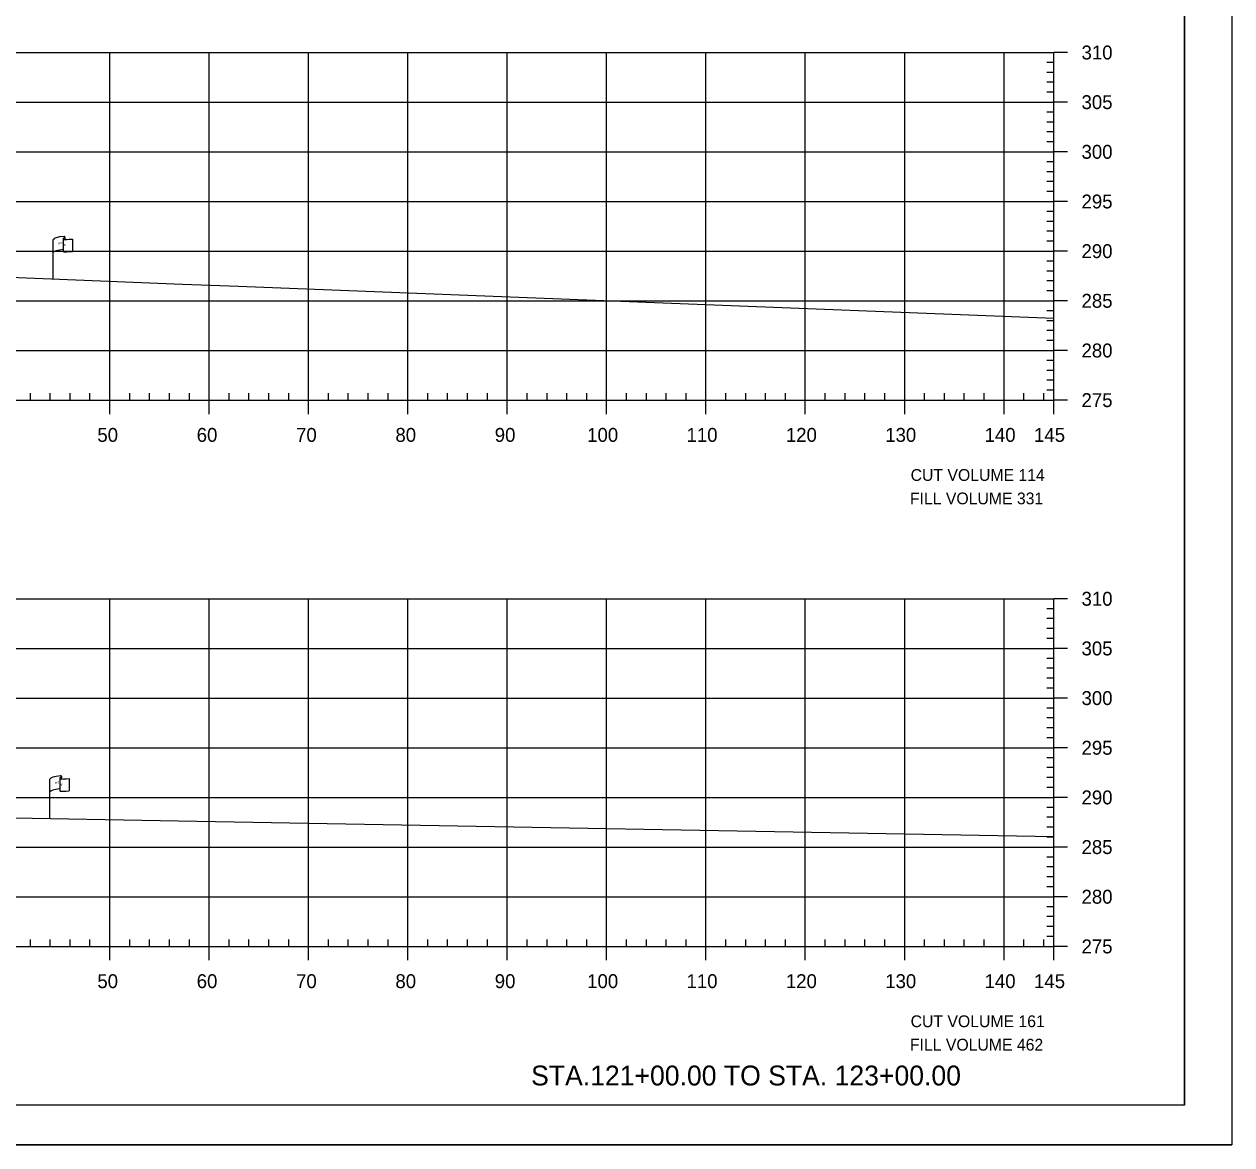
# Model space of a CAD drawing. Extents: x 1370843 to 1371177, y 380307 to 382654.
# Drawn here: x 1371055.1 to 1371176.6, y 382014.2 to 382127 of the extents above; entities that cross this region are included whole.
import ezdxf

# ---------------------------------------------------------------- set-up
doc = ezdxf.new("R2010")
doc.units = 0
for name, color, linetype in [('R_Axis', 7, 'Continuous'), ('R_Axis Annot', 7, 'Continuous'), ('R_Border', 7, 'Continuous'), ('R_Border Notes', 7, 'Continuous'), ('R_Draft', 7, 'Continuous'), ('R_Exist Surface', 7, 'Continuous'), ('R_Grid', 7, 'Continuous'), ('R_No Plot', 7, 'Continuous'), ('R_ROW', 7, 'Continuous')]:
    doc.layers.add(name, color=color, linetype=linetype)

msp = doc.modelspace()

# ---------------------------------------------------------------- linework, layer by layer
at = {"layer": 'R_Axis'}
for p, q in [((1371158.71, 382123.15), (1371158.01, 382123.15)), ((1371158.71, 382089.15), (1371158.71, 382124.15)), ((1371160.11, 382124.15), (1371158.71, 382124.15)), ((1371158.71, 382122.15), (1371158.01, 382122.15)), ((1371158.71, 382121.15), (1371158.01, 382121.15)), ((1371158.71, 382120.15), (1371158.01, 382120.15)), ((1371158.71, 382118.15), (1371158.01, 382118.15)), ((1371160.11, 382119.15), (1371158.71, 382119.15)), ((1371158.71, 382117.15), (1371158.01, 382117.15)), ((1371158.71, 382116.15), (1371158.01, 382116.15)), ((1371158.71, 382115.15), (1371158.01, 382115.15)), ((1371160.11, 382114.15), (1371158.71, 382114.15)), ((1371158.71, 382113.15), (1371158.01, 382113.15)), ((1371158.71, 382112.15), (1371158.01, 382112.15)), ((1371158.71, 382111.15), (1371158.01, 382111.15)), ((1371158.71, 382110.15), (1371158.01, 382110.15)), ((1371160.11, 382109.15), (1371158.71, 382109.15)), ((1371158.71, 382108.15), (1371158.01, 382108.15)), ((1371158.71, 382107.15), (1371158.01, 382107.15)), ((1371158.71, 382106.15), (1371158.01, 382106.15)), ((1371158.71, 382105.15), (1371158.01, 382105.15)), ((1371160.11, 382104.15), (1371158.71, 382104.15)), ((1371158.71, 382103.15), (1371158.01, 382103.15)), ((1371158.71, 382102.15), (1371158.01, 382102.15)), ((1371158.71, 382101.15), (1371158.01, 382101.15)), ((1371158.71, 382100.15), (1371158.01, 382100.15)), ((1371160.11, 382099.15), (1371158.71, 382099.15)), ((1371158.71, 382098.15), (1371158.01, 382098.15)), ((1371158.71, 382097.15), (1371158.01, 382097.15)), ((1371158.71, 382096.15), (1371158.01, 382096.15)), ((1371158.71, 382095.15), (1371158.01, 382095.15)), ((1371160.11, 382094.15), (1371158.71, 382094.15)), ((1371158.71, 382093.15), (1371158.01, 382093.15)), ((1371158.71, 382092.15), (1371158.01, 382092.15)), ((1371158.71, 382091.15), (1371158.01, 382091.15)), ((1370868.71, 382089.15), (1371158.71, 382089.15)), ((1371055.71, 382089.15), (1371055.71, 382089.85)), ((1371057.71, 382089.15), (1371057.71, 382089.85)), ((1371059.71, 382089.15), (1371059.71, 382089.85)), ((1371061.71, 382089.15), (1371061.71, 382089.85)), ((1371063.71, 382087.75), (1371063.71, 382089.15)), ((1371065.71, 382089.15), (1371065.71, 382089.85)), ((1371067.71, 382089.15), (1371067.71, 382089.85)), ((1371069.71, 382089.15), (1371069.71, 382089.85)), ((1371071.71, 382089.15), (1371071.71, 382089.85)), ((1371073.71, 382087.75), (1371073.71, 382089.15)), ((1371075.71, 382089.15), (1371075.71, 382089.85)), ((1371077.71, 382089.15), (1371077.71, 382089.85)), ((1371079.71, 382089.15), (1371079.71, 382089.85)), ((1371081.71, 382089.15), (1371081.71, 382089.85)), ((1371083.71, 382087.75), (1371083.71, 382089.15)), ((1371085.71, 382089.15), (1371085.71, 382089.85)), ((1371087.71, 382089.15), (1371087.71, 382089.85)), ((1371089.71, 382089.15), (1371089.71, 382089.85)), ((1371091.71, 382089.15), (1371091.71, 382089.85)), ((1371093.71, 382087.75), (1371093.71, 382089.15)), ((1371095.71, 382089.15), (1371095.71, 382089.85)), ((1371097.71, 382089.15), (1371097.71, 382089.85)), ((1371099.71, 382089.15), (1371099.71, 382089.85)), ((1371101.71, 382089.15), (1371101.71, 382089.85)), ((1371103.71, 382087.75), (1371103.71, 382089.15)), ((1371105.71, 382089.15), (1371105.71, 382089.85)), ((1371107.71, 382089.15), (1371107.71, 382089.85)), ((1371109.71, 382089.15), (1371109.71, 382089.85)), ((1371111.71, 382089.15), (1371111.71, 382089.85)), ((1371113.71, 382087.75), (1371113.71, 382089.15)), ((1371115.71, 382089.15), (1371115.71, 382089.85)), ((1371117.71, 382089.15), (1371117.71, 382089.85)), ((1371119.71, 382089.15), (1371119.71, 382089.85)), ((1371121.71, 382089.15), (1371121.71, 382089.85)), ((1371123.71, 382087.75), (1371123.71, 382089.15)), ((1371125.71, 382089.15), (1371125.71, 382089.85)), ((1371127.71, 382089.15), (1371127.71, 382089.85)), ((1371129.71, 382089.15), (1371129.71, 382089.85)), ((1371131.71, 382089.15), (1371131.71, 382089.85)), ((1371133.71, 382087.75), (1371133.71, 382089.15)), ((1371135.71, 382089.15), (1371135.71, 382089.85)), ((1371137.71, 382089.15), (1371137.71, 382089.85)), ((1371139.71, 382089.15), (1371139.71, 382089.85)), ((1371141.71, 382089.15), (1371141.71, 382089.85)), ((1371143.71, 382087.75), (1371143.71, 382089.15)), ((1371145.71, 382089.15), (1371145.71, 382089.85)), ((1371147.71, 382089.15), (1371147.71, 382089.85)), ((1371149.71, 382089.15), (1371149.71, 382089.85)), ((1371151.71, 382089.15), (1371151.71, 382089.85)), ((1371153.71, 382087.75), (1371153.71, 382089.15)), ((1371155.71, 382089.15), (1371155.71, 382089.85)), ((1371157.71, 382089.15), (1371157.71, 382089.85)), ((1371158.71, 382090.15), (1371158.01, 382090.15)), ((1371158.71, 382087.75), (1371158.71, 382089.15)), ((1371160.11, 382089.15), (1371158.71, 382089.15)), ((1371158.71, 382034.15), (1371158.71, 382069.15)), ((1371160.11, 382069.15), (1371158.71, 382069.15)), ((1371158.71, 382068.15), (1371158.01, 382068.15)), ((1371158.71, 382067.15), (1371158.01, 382067.15)), ((1371158.71, 382066.15), (1371158.01, 382066.15)), ((1371158.71, 382065.15), (1371158.01, 382065.15)), ((1371160.11, 382064.15), (1371158.71, 382064.15)), ((1371158.71, 382063.15), (1371158.01, 382063.15)), ((1371158.71, 382062.15), (1371158.01, 382062.15)), ((1371158.71, 382061.15), (1371158.01, 382061.15)), ((1371158.71, 382060.15), (1371158.01, 382060.15)), ((1371160.11, 382059.15), (1371158.71, 382059.15)), ((1371158.71, 382058.15), (1371158.01, 382058.15)), ((1371158.71, 382057.15), (1371158.01, 382057.15)), ((1371158.71, 382056.15), (1371158.01, 382056.15)), ((1371158.71, 382055.15), (1371158.01, 382055.15)), ((1371160.11, 382054.15), (1371158.71, 382054.15)), ((1371158.71, 382053.15), (1371158.01, 382053.15)), ((1371158.71, 382052.15), (1371158.01, 382052.15)), ((1371158.71, 382051.15), (1371158.01, 382051.15)), ((1371158.71, 382050.15), (1371158.01, 382050.15)), ((1371160.11, 382049.15), (1371158.71, 382049.15)), ((1371158.71, 382048.15), (1371158.01, 382048.15)), ((1371158.71, 382047.15), (1371158.01, 382047.15)), ((1371158.71, 382046.15), (1371158.01, 382046.15)), ((1371158.71, 382045.15), (1371158.01, 382045.15)), ((1371160.11, 382044.15), (1371158.71, 382044.15)), ((1371158.71, 382043.15), (1371158.01, 382043.15)), ((1371158.71, 382042.15), (1371158.01, 382042.15)), ((1371158.71, 382041.15), (1371158.01, 382041.15)), ((1371158.71, 382040.15), (1371158.01, 382040.15)), ((1371160.11, 382039.15), (1371158.71, 382039.15)), ((1371158.71, 382038.15), (1371158.01, 382038.15)), ((1371158.71, 382037.15), (1371158.01, 382037.15)), ((1371158.71, 382036.15), (1371158.01, 382036.15)), ((1371055.71, 382034.15), (1371055.71, 382034.85)), ((1371057.71, 382034.15), (1371057.71, 382034.85)), ((1371059.71, 382034.15), (1371059.71, 382034.85)), ((1371061.71, 382034.15), (1371061.71, 382034.85)), ((1371065.71, 382034.15), (1371065.71, 382034.85)), ((1371067.71, 382034.15), (1371067.71, 382034.85)), ((1371069.71, 382034.15), (1371069.71, 382034.85)), ((1371071.71, 382034.15), (1371071.71, 382034.85)), ((1371075.71, 382034.15), (1371075.71, 382034.85)), ((1371077.71, 382034.15), (1371077.71, 382034.85)), ((1371079.71, 382034.15), (1371079.71, 382034.85)), ((1371081.71, 382034.15), (1371081.71, 382034.85)), ((1371085.71, 382034.15), (1371085.71, 382034.85)), ((1371087.71, 382034.15), (1371087.71, 382034.85)), ((1371089.71, 382034.15), (1371089.71, 382034.85)), ((1371091.71, 382034.15), (1371091.71, 382034.85)), ((1371095.71, 382034.15), (1371095.71, 382034.85)), ((1371097.71, 382034.15), (1371097.71, 382034.85)), ((1371099.71, 382034.15), (1371099.71, 382034.85)), ((1371101.71, 382034.15), (1371101.71, 382034.85)), ((1371105.71, 382034.15), (1371105.71, 382034.85)), ((1371107.71, 382034.15), (1371107.71, 382034.85)), ((1371109.71, 382034.15), (1371109.71, 382034.85)), ((1371111.71, 382034.15), (1371111.71, 382034.85)), ((1371115.71, 382034.15), (1371115.71, 382034.85)), ((1371117.71, 382034.15), (1371117.71, 382034.85)), ((1371119.71, 382034.15), (1371119.71, 382034.85)), ((1371121.71, 382034.15), (1371121.71, 382034.85)), ((1371125.71, 382034.15), (1371125.71, 382034.85)), ((1371127.71, 382034.15), (1371127.71, 382034.85)), ((1371129.71, 382034.15), (1371129.71, 382034.85)), ((1371131.71, 382034.15), (1371131.71, 382034.85)), ((1371135.71, 382034.15), (1371135.71, 382034.85)), ((1371137.71, 382034.15), (1371137.71, 382034.85)), ((1371139.71, 382034.15), (1371139.71, 382034.85)), ((1371141.71, 382034.15), (1371141.71, 382034.85)), ((1371145.71, 382034.15), (1371145.71, 382034.85)), ((1371147.71, 382034.15), (1371147.71, 382034.85)), ((1371149.71, 382034.15), (1371149.71, 382034.85)), ((1371151.71, 382034.15), (1371151.71, 382034.85)), ((1371155.71, 382034.15), (1371155.71, 382034.85)), ((1371157.71, 382034.15), (1371157.71, 382034.85)), ((1371158.71, 382035.15), (1371158.01, 382035.15)), ((1370868.71, 382034.15), (1371158.71, 382034.15)), ((1371063.71, 382032.75), (1371063.71, 382034.15)), ((1371073.71, 382032.75), (1371073.71, 382034.15)), ((1371083.71, 382032.75), (1371083.71, 382034.15)), ((1371093.71, 382032.75), (1371093.71, 382034.15)), ((1371103.71, 382032.75), (1371103.71, 382034.15)), ((1371113.71, 382032.75), (1371113.71, 382034.15)), ((1371123.71, 382032.75), (1371123.71, 382034.15)), ((1371133.71, 382032.75), (1371133.71, 382034.15)), ((1371143.71, 382032.75), (1371143.71, 382034.15)), ((1371153.71, 382032.75), (1371153.71, 382034.15)), ((1371158.71, 382032.75), (1371158.71, 382034.15)), ((1371160.11, 382034.15), (1371158.71, 382034.15))]:
    msp.add_line(p, q, dxfattribs=at)
at = {"layer": 'R_Border'}
for q in [(1371171.89, 382223.61), (1370855.71, 382018.15)]:
    msp.add_line((1371171.89, 382018.15), q, dxfattribs=at)
at = {"layer": 'R_Exist Surface'}
for p, q in [((1371076.66, 382100.61), (1371158.71, 382097.39)), ((1371072.46, 382046.77), (1371158.71, 382045.22))]:
    msp.add_line(p, q, dxfattribs=at)
for points in [[(1370921.23, 382100.29), (1370921.61, 382100.23), (1370937.63, 382100.82), (1370961.82, 382101.77), (1370979.86, 382106.36), (1370981.34, 382106.74), (1370981.8, 382106.81), (1370987.82, 382107.67), (1370988.64, 382107.69), (1370999.17, 382107.94), (1370999.85, 382107.91), (1371008.58, 382107.56), (1371016.29, 382106.64), (1371016.42, 382106.63), (1371016.6, 382106.58), (1371022.64, 382105.04), (1371028.47, 382103.56), (1371028.64, 382103.51), (1371029, 382103.47), (1371041.26, 382102.03), (1371071.02, 382100.83), (1371076.66, 382100.61)], [(1370913.3, 382044.81), (1370913.49, 382044.81), (1370925.46, 382045.14), (1370954.42, 382045.95), (1370970.4, 382050.35), (1370975.86, 382051.82), (1370977.13, 382051.98), (1370981.24, 382052.53), (1370983.59, 382052.58), (1370992.86, 382052.74), (1370994.81, 382052.65), (1371001.83, 382052.35), (1371003.31, 382052.16), (1371009.26, 382051.49), (1371020.73, 382048.37), (1371022.75, 382047.86), (1371028.21, 382047.57), (1371072.46, 382046.77)]]:
    msp.add_lwpolyline(points, dxfattribs=at)
at = {"layer": 'R_Grid'}
for p, q in [((1370868.71, 382124.15), (1371158.71, 382124.15)), ((1371063.71, 382089.15), (1371063.71, 382124.15)), ((1371073.71, 382089.15), (1371073.71, 382124.15)), ((1371083.71, 382089.15), (1371083.71, 382124.15)), ((1371093.71, 382089.15), (1371093.71, 382124.15)), ((1371103.71, 382089.15), (1371103.71, 382124.15)), ((1371113.71, 382089.15), (1371113.71, 382124.15)), ((1371123.71, 382089.15), (1371123.71, 382124.15)), ((1371133.71, 382089.15), (1371133.71, 382124.15)), ((1371143.71, 382089.15), (1371143.71, 382124.15)), ((1371153.71, 382089.15), (1371153.71, 382124.15)), ((1371158.71, 382089.15), (1371158.71, 382124.15)), ((1370868.71, 382119.15), (1371158.71, 382119.15)), ((1370868.71, 382114.15), (1371158.71, 382114.15)), ((1370868.71, 382109.15), (1371158.71, 382109.15)), ((1370868.71, 382104.15), (1371158.71, 382104.15)), ((1370868.71, 382099.15), (1371158.71, 382099.15)), ((1370868.71, 382094.15), (1371158.71, 382094.15)), ((1370868.71, 382089.15), (1371158.71, 382089.15)), ((1370868.71, 382069.15), (1371158.71, 382069.15)), ((1371063.71, 382034.15), (1371063.71, 382069.15)), ((1371073.71, 382034.15), (1371073.71, 382069.15)), ((1371083.71, 382034.15), (1371083.71, 382069.15)), ((1371093.71, 382034.15), (1371093.71, 382069.15)), ((1371103.71, 382034.15), (1371103.71, 382069.15)), ((1371113.71, 382034.15), (1371113.71, 382069.15)), ((1371123.71, 382034.15), (1371123.71, 382069.15)), ((1371133.71, 382034.15), (1371133.71, 382069.15)), ((1371143.71, 382034.15), (1371143.71, 382069.15)), ((1371153.71, 382034.15), (1371153.71, 382069.15)), ((1371158.71, 382034.15), (1371158.71, 382069.15)), ((1370868.71, 382064.15), (1371158.71, 382064.15)), ((1370868.71, 382059.15), (1371158.71, 382059.15)), ((1370868.71, 382054.15), (1371158.71, 382054.15)), ((1370868.71, 382049.15), (1371158.71, 382049.15)), ((1370868.71, 382044.15), (1371158.71, 382044.15)), ((1370868.71, 382039.15), (1371158.71, 382039.15)), ((1370868.71, 382034.15), (1371158.71, 382034.15))]:
    msp.add_line(p, q, dxfattribs=at)
at = {"layer": 'R_No Plot'}
msp.add_line((1370843.31, 382014.17), (1371176.64, 382014.17), dxfattribs=at)
for points in [[(1370843.3, 382227.51), (1371176.64, 382227.51), (1371176.64, 382014.17), (1370843.3, 382014.17)], [(1371089.63, 382223.61), (1371089.63, 382213.73), (1371125.36, 382213.73), (1371125.36, 382210.81), (1371148.56, 382210.81), (1371148.56, 382186.48), (1371171.89, 382186.48), (1371171.89, 382018.15), (1370855.71, 382018.15), (1370855.71, 382223.61)]]:
    msp.add_lwpolyline(points, close=True, dxfattribs=at)
at = {"layer": 'R_ROW'}
for p, q in [((1371058.01, 382101.36), (1371058.01, 382105.31)), ((1371059.01, 382105.4), (1371059.01, 382105.39)), ((1371059.01, 382105.39), (1371059.01, 382104.16)), ((1371059.18, 382105.56), (1371059.18, 382105.32)), ((1371059.94, 382105.37), (1371059.94, 382104.13)), ((1371057.68, 382047.04), (1371057.68, 382050.99)), ((1371058.67, 382051.09), (1371058.67, 382051.07)), ((1371058.67, 382051.07), (1371058.67, 382049.85)), ((1371058.84, 382051.24), (1371058.84, 382051)), ((1371059.61, 382051.05), (1371059.61, 382049.81))]:
    msp.add_line(p, q, dxfattribs=at)
for centre, radius, start, end in [((1371059.09, 382105.4), 0.078, 88.6458, 274.2828), ((1371059.1, 382105.56), 0.0783, 263.0712, 93.9564), ((1371059.09, 382104.16), 0.0783, 180, 273.9564), ((1371058.76, 382051.24), 0.0783, 263.0712, 93.9564), ((1371058.75, 382051.09), 0.078, 88.6458, 274.2828), ((1371058.75, 382049.85), 0.0783, 180, 273.9564)]:
    msp.add_arc(centre, radius, start, end, dxfattribs=at)
for centre, major_axis, ratio, start_param, end_param in [((1371059.6, 382105.35), (-1.58, -0.04), 0.19887, 5.030368, 6.283185), ((1371060.3, 382105.47), (-1.23, -0.13), 0.052933, 0.159456, 1.268315), ((1371059.59, 382104.03), (-1.58, -0.04), 0.19887, 5.083035, 6.194897), ((1371060.3, 382104.23), (-1.23, -0.13), 0.052933, 0.159456, 1.268315), ((1371059.26, 382051.04), (-1.58, -0.04), 0.19887, 5.030368, 6.283185), ((1371059.97, 382051.15), (-1.23, -0.13), 0.052933, 0.159456, 1.268315), ((1371059.25, 382049.72), (-1.58, -0.04), 0.19887, 5.083035, 6.194897), ((1371059.97, 382049.91), (-1.23, -0.13), 0.052933, 0.159456, 1.268315)]:
    msp.add_ellipse(centre, major_axis=major_axis, ratio=ratio, start_param=start_param, end_param=end_param, dxfattribs=at)

# ---------------------------------------------------------------- texts
at = {"layer": 'R_Axis Annot'}
for s, p in [('310', (1371161.51, 382123.45)), ('305', (1371161.51, 382118.45)), ('300', (1371161.51, 382113.45)), ('295', (1371161.51, 382108.45)), ('290', (1371161.51, 382103.45)), ('285', (1371161.51, 382098.45)), ('280', (1371161.51, 382093.45)), ('275', (1371161.51, 382088.45)), ('50', (1371062.45, 382084.95)), ('60', (1371072.45, 382084.95)), ('70', (1371082.45, 382084.95)), ('80', (1371092.45, 382084.95)), ('90', (1371102.45, 382084.95)), ('100', (1371111.75, 382084.95)), ('110', (1371121.75, 382084.95)), ('120', (1371131.75, 382084.95)), ('130', (1371141.75, 382084.95)), ('140', (1371151.75, 382084.95)), ('145', (1371156.73, 382084.95)), ('310', (1371161.51, 382068.45)), ('305', (1371161.51, 382063.45)), ('300', (1371161.51, 382058.45)), ('295', (1371161.51, 382053.45)), ('290', (1371161.51, 382048.45)), ('285', (1371161.51, 382043.45)), ('280', (1371161.51, 382038.45)), ('275', (1371161.51, 382033.45)), ('50', (1371062.45, 382029.95)), ('60', (1371072.45, 382029.95)), ('70', (1371082.45, 382029.95)), ('80', (1371092.45, 382029.95)), ('90', (1371102.45, 382029.95)), ('100', (1371111.75, 382029.95)), ('110', (1371121.75, 382029.95)), ('120', (1371131.75, 382029.95)), ('130', (1371141.75, 382029.95)), ('140', (1371151.75, 382029.95)), ('145', (1371156.73, 382029.95))]:
    msp.add_text(s, height=1.4, dxfattribs=at).set_placement(p)
at = {"layer": 'R_Border Notes'}
for s, p in [('CUT VOLUME 114', (1371144.31, 382081.02)), ('FILL VOLUME 331', (1371144.24, 382078.66)), ('CUT VOLUME 161', (1371144.31, 382026.02)), ('FILL VOLUME 462', (1371144.24, 382023.66))]:
    msp.add_text(s, height=1.1875, dxfattribs=at).set_placement(p)
at = {"layer": 'R_Draft'}
msp.add_text('STA.121+00.00 TO STA. 123+00.00', height=2, dxfattribs=at).set_placement((1371106.11, 382020.15))
at = {"layer": 'R_ROW'}
for s, height, rotation, p in [('R ', 0.2, 9.9884, (1371058.53, 382104.81)), (' O', 0.2, 9.9884, (1371058.68, 382104.85)), ('W', 0.2, 351.1788, (1371059.01, 382104.69)), ('DWB 11-9-07', 0.001, 90, (1371059.18, 382105.32)), ('DWB 11-9-07', 0.001, 5.0717, (1371059.93, 382104.12)), ('DWB 11-9-07', 0.001, 90, (1371058.01, 382101.36)), ('R ', 0.2, 9.9884, (1371058.2, 382050.49)), (' O', 0.2, 9.9884, (1371058.34, 382050.54)), ('W', 0.2, 351.1788, (1371058.67, 382050.37)), ('DWB 11-9-07', 0.001, 90, (1371058.84, 382051)), ('DWB 11-9-07', 0.001, 5.0717, (1371059.6, 382049.81)), ('DWB 11-9-07', 0.001, 90, (1371057.68, 382047.04))]:
    msp.add_text(s, height=height, rotation=rotation, dxfattribs=at).set_placement(p)

doc.saveas('drawing.dxf')
